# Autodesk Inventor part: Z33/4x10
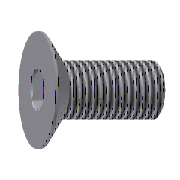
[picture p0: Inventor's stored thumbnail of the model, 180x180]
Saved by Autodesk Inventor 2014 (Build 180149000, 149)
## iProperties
Created: 2009-11
Part Number: Z33/4x10
Material: Steel, Mild
Description: Countersunk Socket Head Screw
Document SubType Name: Modeling
Designer: gaom
Standard Revision: 1
Manufacturer: HASCO
Language: en-US
Size Designation: 4x10
Categories: <MemberInstance><Categories><Category DisplayName="Mold" InternalName="349578f2-f4d4-4954-8c09-8e99297a61c0" Mnemonic="MOLD"><Category DisplayName="Fasteners" I
Mass: 0.132503 g
Surface Area: 2.09825 cm^2
Volume: 0.132503 cm^3
Density: 7.86 g/cm^3
Appearance: Steel
IsCustomPart: 0
Author: gaom
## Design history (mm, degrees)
sketch "Sketch1"
  geometry: L1 (0, 1.443)-(0, 4); L2 (0, 4)-(0.3, 4); L3 (0.3, 4)-(2.3, 2); L4 (2.3, 2)-(10, 2); L5 (10, 2)-(10, 0); L6 (0.193, 1.25)-(2, 1.25); L7 (2, 1.25)-(2.751, 0); L8 (12, 0)-(-2, 0) reference; L9 (0.193, 1.25)-(0, 1.443); L10 (2.751, 0)-(10, 0); 1 further point
  constraints: 18 end point, 3 point on line, 2 parallel, 1 horizontal, 1 perpendicular, 1 vertical
  dimensions: "d1" = 10 distance between parallel lines of L5 L1 (= L); "d2" = 2.3 distance from line of L3.end L1 (= k); "d8" = 8 diameter of L2 L8 (= dk); "d9" = 2.5 diameter of L6 L8 (= sw); "d10" = 59 deg angle of L7 L8; "d11" = 45 deg angle of L3 L8 (= 0.5 x A_); "d12" = 4 diameter of L4 L8 (= d); "d14" = 45 deg angle of L8 L9; "d15" = 2 distance from line of L6.end L1 (= t); "d16" = 2.88675 diameter of L1.start L8 (= 1.1547 x sw)
revolve "Revolution1" sketch "Sketch1" stored, may be unused: angle "d39" = 90 deg
sketch "Sketch2"
  geometry: L1 (0, 1.443)-(1.25, 0.722); L2 (1.25, 0.722)-(1.25, -0.722); L3 (1.25, -0.722)-(0, -1.443); L4 (0, -1.443)-(-1.25, -0.722); L5 (-1.25, -0.722)-(-1.25, 0.722); L6 (-1.25, 0.722)-(0, 1.443); 2 further points
  constraints: 12 end point, 2 vertical alignment, 1 coincident, 14 other
extrude "Extrusion1" cut sketch "Sketch2" taper "d3" = 0 deg; stored distance "d40" = 10
thread "Thread1" dims "d4" = 7.7 (= b), "d5" = 0
body "Solid1"
chamfer "Chamfer1" distance "d17" = 0.35 (= 0.5 x P); stored, may be unused: second distance "d37" = 2, angle "d38" = 45 deg
other parameters: "d" = 4 [user parameter; used in 1 equation term], "L" = 10 [user parameter; used in 1 equation term], "b" = 7.7 [user parameter; used in 1 equation term], "dk" = 8 [user parameter; used in 1 equation term], "k" = 2.3 [user parameter; used in 1 equation term], "sw" = 2.5 [user parameter; used in 2 equation terms], "P" = 0.7 [user parameter; used in 1 equation term], "t" = 2 [user parameter; used in 1 equation term], "d7" = 0, "A_" = 90 deg [user parameter; used in 1 equation term], "d41" = 0
